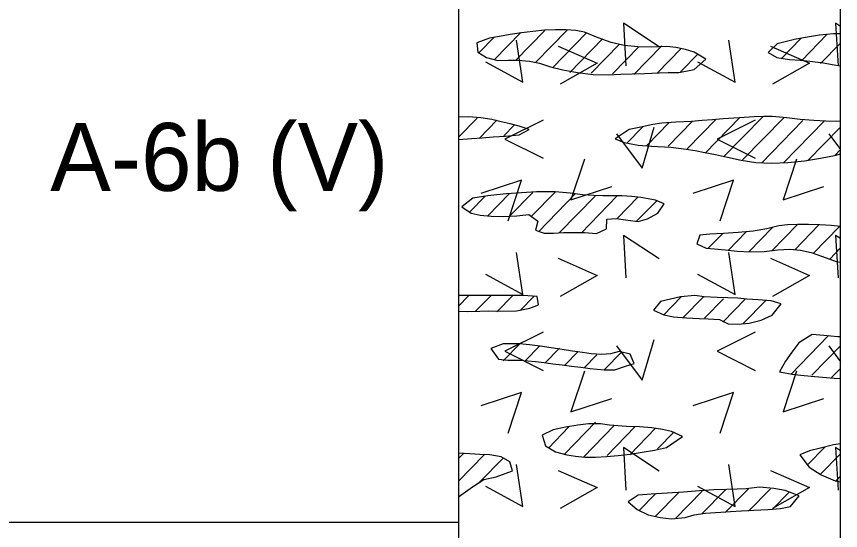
# Model space of a CAD drawing. Extents: x -0.01 to 0.83, y -0.63 to 1.27.
# Drawn here: x 0.7524 to 0.8333, y 1.0754 to 1.1259 of the extents above; entities that cross this region are included whole.
import ezdxf

# ---------------------------------------------------------------- set-up
doc = ezdxf.new("R2010")
doc.units = 0

msp = doc.modelspace()

# ---------------------------------------------------------------- linework, layer by layer
for points in [[(0, 0), (0.833332, 0), (0.833332, 1.274997), (0, 1.274997)], [(0, 0), (0.833332, 0), (0.833332, 1.274997), (0, 1.274997)], [(0, 0), (0.833332, 0), (0.833332, 1.274997), (0, 1.274997)], [(0, 0), (0.833332, 0), (0.833332, 1.274997), (0, 1.274997)], [(0, 0), (0.833332, 0), (0.833332, 1.274997), (0, 1.274997)], [(0.798854, 1.123778), (0.797634, 1.123317), (0.797728, 1.122422), (0.798587, 1.121898), (0.799696, 1.121602), (0.800742, 1.121612), (0.801652, 1.121626), (0.802809, 1.121543), (0.803766, 1.121335), (0.804856, 1.120986), (0.80606, 1.120689), (0.807509, 1.120415), (0.809046, 1.120229), (0.810517, 1.120199), (0.811769, 1.120256), (0.812889, 1.120297), (0.814075, 1.120332), (0.815527, 1.120372), (0.816416, 1.120398), (0.817445, 1.12043), (0.818967, 1.120703), (0.820111, 1.121739), (0.818963, 1.122408), (0.818099, 1.122676), (0.817169, 1.122872), (0.816265, 1.122977), (0.814793, 1.122918), (0.813435, 1.122921), (0.812104, 1.123071), (0.810802, 1.123373), (0.809527, 1.123834), (0.808198, 1.124383), (0.807356, 1.124543), (0.806403, 1.124617), (0.805364, 1.124618), (0.804267, 1.124558), (0.803138, 1.124449), (0.802006, 1.124304), (0.800896, 1.124136), (0.799837, 1.123956)], [(0.832629, 1.124225), (0.831261, 1.124087), (0.829688, 1.123822), (0.828826, 1.123648), (0.82712, 1.123238), (0.826226, 1.122369), (0.827084, 1.121877), (0.828308, 1.12169), (0.829408, 1.121625), (0.830335, 1.121536), (0.831655, 1.121353), (0.832526, 1.121211), (0.833332, 1.121069), (0.833332, 1.124217)], [(0.795832, 1.113822), (0.797147, 1.113932), (0.798141, 1.114005), (0.799224, 1.114082), (0.800394, 1.114167), (0.80179, 1.114289), (0.802748, 1.114804), (0.801793, 1.115146), (0.800911, 1.11536), (0.800027, 1.11558), (0.79909, 1.115787), (0.798029, 1.115952), (0.79677, 1.116048), (0.795832, 1.116027)], [(0.828162, 1.111574), (0.82978, 1.111743), (0.831374, 1.111995), (0.832902, 1.112306), (0.833332, 1.112411), (0.833332, 1.115651), (0.832951, 1.115618), (0.831885, 1.11564), (0.830714, 1.115693), (0.829383, 1.115795), (0.828069, 1.115965), (0.826619, 1.116084), (0.825765, 1.116086), (0.824843, 1.116059), (0.823868, 1.116008), (0.822856, 1.11594), (0.82182, 1.11586), (0.820774, 1.115776), (0.819735, 1.115693), (0.818715, 1.115618), (0.817148, 1.115523), (0.815785, 1.11543), (0.814914, 1.115297), (0.813574, 1.115023), (0.812595, 1.11481), (0.811206, 1.113892), (0.812105, 1.113529), (0.813452, 1.113284), (0.814789, 1.113193), (0.816678, 1.11309), (0.818181, 1.11289), (0.819046, 1.112744), (0.820004, 1.112565), (0.821067, 1.112351), (0.82225, 1.112099), (0.823565, 1.111807), (0.825013, 1.111582), (0.826559, 1.111512)], [(0.797084, 1.106592), (0.797938, 1.106414), (0.799042, 1.106302), (0.800285, 1.106268), (0.801555, 1.106322), (0.802742, 1.106477), (0.803614, 1.105815), (0.803377, 1.104918), (0.804221, 1.104648), (0.805167, 1.104629), (0.806129, 1.104685), (0.807202, 1.104716), (0.808182, 1.104685), (0.809387, 1.104611), (0.81037, 1.105077), (0.81038, 1.106024), (0.811296, 1.106086), (0.812442, 1.105899), (0.813463, 1.105793), (0.814379, 1.106049), (0.815394, 1.106592), (0.816006, 1.107504), (0.81517, 1.107877), (0.813738, 1.108153), (0.812849, 1.108246), (0.811872, 1.108304), (0.810001, 1.108306), (0.809104, 1.108324), (0.808002, 1.108398), (0.806784, 1.108555), (0.805305, 1.108686), (0.804427, 1.108699), (0.803488, 1.108683), (0.802511, 1.108642), (0.801521, 1.10858), (0.80054, 1.108502), (0.799593, 1.108411), (0.798702, 1.108312), (0.797221, 1.108089), (0.796138, 1.107211)], [(0.832407, 1.105373), (0.831293, 1.105438), (0.830172, 1.105474), (0.829096, 1.105477), (0.828115, 1.105438), (0.827281, 1.10535), (0.826083, 1.10505), (0.824762, 1.104824), (0.823296, 1.104687), (0.821831, 1.104605), (0.820509, 1.104546), (0.819505, 1.104447), (0.819224, 1.103583), (0.820125, 1.103164), (0.820967, 1.103112), (0.821997, 1.103013), (0.823181, 1.102883), (0.824476, 1.102794), (0.825838, 1.102819), (0.82719, 1.102984), (0.828356, 1.10305), (0.829402, 1.102969), (0.830435, 1.102736), (0.831559, 1.102345), (0.832909, 1.101855), (0.833332, 1.101779), (0.833332, 1.105298)], [(0.795832, 1.09696), (0.796757, 1.09695), (0.797925, 1.096969), (0.798816, 1.097008), (0.799915, 1.096965), (0.801515, 1.097009), (0.802823, 1.097266), (0.803666, 1.097585), (0.80354, 1.098424), (0.802165, 1.098509), (0.795832, 1.098509)], [(0.818216, 1.096315), (0.819444, 1.096257), (0.820325, 1.096216), (0.821453, 1.096148), (0.822286, 1.095734), (0.82324, 1.09569), (0.824378, 1.095795), (0.825554, 1.096084), (0.826624, 1.096588), (0.82749, 1.097685), (0.826513, 1.097988), (0.825239, 1.098089), (0.82413, 1.098153), (0.823236, 1.098259), (0.822257, 1.098278), (0.821211, 1.098302), (0.819948, 1.098394), (0.819024, 1.098509), (0.817611, 1.09837), (0.815663, 1.097926), (0.814958, 1.097087), (0.815983, 1.096599), (0.816947, 1.096423)], [(0.833053, 1.094461), (0.831709, 1.094573), (0.830539, 1.094674), (0.829246, 1.093854), (0.828567, 1.09294), (0.827924, 1.092053), (0.827345, 1.091027), (0.828579, 1.090801), (0.829451, 1.0907), (0.830451, 1.090604), (0.831549, 1.090508), (0.832716, 1.090411), (0.833332, 1.09036), (0.833332, 1.094452)], [(0.800664, 1.092158), (0.801881, 1.092152), (0.803392, 1.092023), (0.804229, 1.091927), (0.805103, 1.091817), (0.806004, 1.091699), (0.806919, 1.091578), (0.807838, 1.09146), (0.808747, 1.09135), (0.810142, 1.091208), (0.811186, 1.09122), (0.812223, 1.091565), (0.81308, 1.09185), (0.812673, 1.092752), (0.811597, 1.092999), (0.810749, 1.092801), (0.809892, 1.092718), (0.808847, 1.092799), (0.807995, 1.09291), (0.807033, 1.093055), (0.805997, 1.093218), (0.804922, 1.093385), (0.803843, 1.093542), (0.802797, 1.093674), (0.801817, 1.093766), (0.800202, 1.093775), (0.799007, 1.093302), (0.79974, 1.09226)], [(0.812326, 1.085653), (0.810635, 1.085772), (0.809773, 1.085905), (0.808601, 1.085912), (0.807553, 1.085768), (0.806321, 1.085569), (0.805133, 1.085326), (0.804031, 1.084805), (0.804359, 1.083744), (0.805363, 1.083177), (0.806466, 1.082879), (0.807303, 1.082728), (0.80824, 1.082652), (0.80926, 1.082643), (0.810349, 1.082694), (0.811489, 1.082796), (0.812666, 1.082943), (0.813863, 1.083127), (0.815063, 1.08334), (0.816252, 1.083574), (0.81783, 1.084655), (0.816735, 1.085154), (0.815852, 1.085357), (0.814797, 1.085514), (0.813609, 1.085616)], [(0.832654, 1.08384), (0.831362, 1.083531), (0.830275, 1.083256), (0.829339, 1.082862), (0.830265, 1.081662), (0.831418, 1.080899), (0.832792, 1.080321), (0.833332, 1.080222), (0.833332, 1.083931)], [(0.795832, 1.078744), (0.79719, 1.079734), (0.798312, 1.080436), (0.799509, 1.080707), (0.801112, 1.081308), (0.800861, 1.082192), (0.800021, 1.082668), (0.798893, 1.082862), (0.797908, 1.082892), (0.796943, 1.082949), (0.795832, 1.083032)], [(0.825375, 1.079687), (0.824078, 1.079537), (0.823187, 1.07948), (0.822142, 1.079456), (0.820907, 1.079419), (0.819474, 1.079327), (0.817918, 1.079207), (0.816318, 1.079087), (0.814751, 1.078994), (0.813476, 1.078893), (0.812472, 1.078254), (0.813366, 1.077493), (0.814436, 1.076989), (0.815612, 1.0767), (0.816749, 1.076595), (0.818067, 1.076707), (0.818959, 1.076983), (0.820031, 1.077127), (0.821573, 1.077249), (0.82253, 1.077307), (0.823615, 1.077366), (0.824832, 1.077427), (0.826183, 1.077493), (0.827451, 1.077601), (0.828416, 1.077777), (0.829268, 1.078832), (0.827909, 1.079348), (0.826788, 1.079548)]]:
    msp.add_lwpolyline(points, close=True)
for points in [[(0.795832, 1.220831), (0.795832, -0.621832)], [(0.833332, -0.621832), (0.833332, 1.138431)], [(0.806532, 1.124609), (0.803395, 1.121394)], [(0.815512, 1.122941), (0.812012, 1.125254), (0.812262, 1.121066)], [(0.833332, 1.124932), (0.832845, 1.125254), (0.833095, 1.121066)], [(0.799375, 1.123914), (0.797863, 1.122364)], [(0.799328, 1.121652), (0.801951, 1.12434)], [(0.801419, 1.121582), (0.804299, 1.124533)], [(0.805059, 1.120886), (0.808397, 1.124307)], [(0.827512, 1.121761), (0.82945, 1.123746)], [(0.832025, 1.124173), (0.829489, 1.121574)], [(0.798466, 1.121459), (0.802154, 1.119459), (0.801529, 1.123584)], [(0.805617, 1.123004), (0.809456, 1.12132), (0.805806, 1.119259)], [(0.809973, 1.123709), (0.806747, 1.120403)], [(0.811636, 1.123201), (0.808841, 1.120337)], [(0.813032, 1.120205), (0.815789, 1.123031)], [(0.8193, 1.121459), (0.822987, 1.119459), (0.822362, 1.123584)], [(0.82645, 1.123004), (0.83029, 1.12132), (0.826639, 1.119259)], [(0.831379, 1.121298), (0.833332, 1.123299)], [(0.813527, 1.122925), (0.810936, 1.120271)], [(0.815342, 1.12036), (0.817681, 1.122756)], [(0.817605, 1.120465), (0.819344, 1.122248)], [(0.833327, 1.121082), (0.833332, 1.121087)], [(0.797655, 1.115935), (0.795832, 1.114066)], [(0.799604, 1.115719), (0.797864, 1.113937)], [(0.804125, 1.115746), (0.800375, 1.113871), (0.804125, 1.111996)], [(0.818285, 1.112914), (0.821137, 1.115836)], [(0.820035, 1.112494), (0.823455, 1.115999)], [(0.824958, 1.115746), (0.821208, 1.113871), (0.824958, 1.111996)], [(0.825691, 1.116076), (0.82184, 1.112131)], [(0.827752, 1.115976), (0.823702, 1.111827)], [(0.829644, 1.115702), (0.825565, 1.111523)], [(0.801295, 1.11524), (0.800268, 1.114188)], [(0.811342, 1.114405), (0.813842, 1.11103), (0.815029, 1.11503)], [(0.813923, 1.115082), (0.812354, 1.113475)], [(0.814303, 1.113259), (0.816499, 1.115508)], [(0.816395, 1.11319), (0.818789, 1.115644)], [(0.831735, 1.115632), (0.827743, 1.111542)], [(0.833332, 1.115055), (0.830118, 1.111762)], [(0.832175, 1.114405), (0.833332, 1.112843)], [(0.832808, 1.112306), (0.833332, 1.112842)], [(0.808181, 1.111914), (0.806868, 1.107914), (0.810868, 1.109227)], [(0.829014, 1.111914), (0.827702, 1.107914), (0.831702, 1.109227)], [(0.800689, 1.105834), (0.802002, 1.109834), (0.798002, 1.108521)], [(0.821523, 1.105834), (0.822835, 1.109834), (0.818835, 1.108521)], [(0.79871, 1.106335), (0.800849, 1.108526)], [(0.800827, 1.106291), (0.803111, 1.108631)], [(0.805344, 1.108706), (0.802987, 1.106291)], [(0.80367, 1.104779), (0.807321, 1.10852)], [(0.798444, 1.108275), (0.796912, 1.106705)], [(0.805714, 1.104661), (0.809241, 1.108275)], [(0.811418, 1.108292), (0.807854, 1.10464)], [(0.811407, 1.106068), (0.81348, 1.108193)], [(0.815282, 1.107827), (0.813313, 1.105809)], [(0.824327, 1.102804), (0.82666, 1.105194)], [(0.829094, 1.105477), (0.826565, 1.102884)], [(0.828848, 1.103012), (0.831218, 1.10544)], [(0.833245, 1.105305), (0.830651, 1.102646)], [(0.815512, 1.102108), (0.812012, 1.10442), (0.812262, 1.100233)], [(0.820346, 1.10315), (0.821763, 1.104602)], [(0.822335, 1.102976), (0.824076, 1.10476)], [(0.833332, 1.104099), (0.832845, 1.10442), (0.833095, 1.100233)], [(0.798466, 1.100625), (0.802154, 1.098625), (0.801529, 1.10275)], [(0.8193, 1.100625), (0.822987, 1.098625), (0.822362, 1.10275)], [(0.833332, 1.10318), (0.832267, 1.102088)], [(0.805617, 1.102171), (0.809456, 1.100487), (0.805806, 1.098425)], [(0.82645, 1.102171), (0.83029, 1.100487), (0.826639, 1.098425)], [(0.795832, 1.097479), (0.796808, 1.098479)], [(0.798985, 1.098497), (0.797473, 1.096948)], [(0.801161, 1.098514), (0.799593, 1.096907)], [(0.803281, 1.098474), (0.801883, 1.097042)], [(0.817701, 1.098373), (0.815961, 1.09659)], [(0.819878, 1.098391), (0.817852, 1.096314)], [(0.821854, 1.098202), (0.819972, 1.096274)], [(0.824002, 1.098191), (0.821778, 1.095911)], [(0.826007, 1.098033), (0.823783, 1.095754)], [(0.804125, 1.094913), (0.800375, 1.093038), (0.804125, 1.091163)], [(0.824958, 1.094913), (0.821208, 1.093038), (0.824958, 1.091163)], [(0.801877, 1.093814), (0.800195, 1.09209)], [(0.811342, 1.093572), (0.813842, 1.090197), (0.815029, 1.094197)], [(0.832167, 1.094587), (0.828441, 1.09077)], [(0.803798, 1.093569), (0.80237, 1.092107)], [(0.805745, 1.093352), (0.804291, 1.091862)], [(0.80758, 1.093019), (0.806268, 1.091674)], [(0.811876, 1.092996), (0.810165, 1.091242)], [(0.833332, 1.093568), (0.830521, 1.090688)], [(0.832175, 1.093572), (0.833332, 1.09201)], [(0.809414, 1.092686), (0.808159, 1.0914)], [(0.808181, 1.091081), (0.806868, 1.087081), (0.810868, 1.088393)], [(0.829014, 1.091081), (0.827702, 1.087081), (0.831702, 1.088393)], [(0.833332, 1.091355), (0.832451, 1.090453)], [(0.800689, 1.085001), (0.802002, 1.089001), (0.798002, 1.087688)], [(0.821523, 1.085001), (0.822835, 1.089001), (0.818835, 1.087688)], [(0.806256, 1.082969), (0.809278, 1.086066)], [(0.80809, 1.082636), (0.811113, 1.085734)], [(0.804649, 1.083536), (0.806674, 1.085611)], [(0.810409, 1.0828), (0.813175, 1.085634)], [(0.812643, 1.082876), (0.815181, 1.085476)], [(0.815361, 1.083448), (0.816987, 1.085114)], [(0.815512, 1.081275), (0.812012, 1.083587), (0.812262, 1.0794)], [(0.830098, 1.081874), (0.831838, 1.083657)], [(0.833332, 1.083265), (0.832845, 1.083587), (0.833095, 1.0794)], [(0.796303, 1.08299), (0.795832, 1.082507)], [(0.798338, 1.082862), (0.795832, 1.080294)], [(0.797862, 1.080162), (0.800229, 1.082587)], [(0.831305, 1.080899), (0.833332, 1.082975)], [(0.798466, 1.079792), (0.802154, 1.077792), (0.801529, 1.081917)], [(0.8193, 1.079792), (0.822987, 1.077792), (0.822362, 1.081917)], [(0.805617, 1.081337), (0.809456, 1.079654), (0.805806, 1.077592)], [(0.82645, 1.081337), (0.83029, 1.079654), (0.826639, 1.077592)], [(0.832854, 1.080273), (0.833332, 1.080762)], [(0.817092, 1.076579), (0.819744, 1.079295)], [(0.819696, 1.077034), (0.822034, 1.079431)], [(0.822015, 1.077197), (0.824297, 1.079535)], [(0.824306, 1.077332), (0.826445, 1.079524)], [(0.826625, 1.077496), (0.828336, 1.079249)], [(0.815192, 1.079058), (0.813538, 1.077362)], [(0.815145, 1.076796), (0.817482, 1.079191)], [(0.749999, 1.076248), (0.795832, 1.076248)]]:
    msp.add_lwpolyline(points)

# ---------------------------------------------------------------- texts
msp.add_text('A-6b (V)', height=0.0066667).set_placement((0.755748, 1.108789))

doc.saveas('drawing.dxf')
